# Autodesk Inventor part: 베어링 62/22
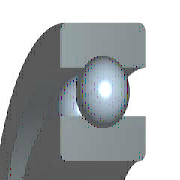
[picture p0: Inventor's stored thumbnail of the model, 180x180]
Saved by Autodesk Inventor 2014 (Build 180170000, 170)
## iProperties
Created: 2009-02
Part Number: 베어링 62/22
Material: 강, 연강
Description: 깊은 그루브 볼 베어링
Document SubType Name: Modeling
Standard: KS B 2023
Designer: KYOUNG IL JANG
Standards Organization: KS
Language: ko-KR
Size Designation: 62/22 - 22 x 50 x 14
Categories: <MemberInstance><Categories><Category DisplayName="샤프트 부품" InternalName="7f7aeb1f-a693-4053-b835-cee3144e0d98" Mnemonic="SHFT"><Category DisplayName="베어링" Inter
Density: 7.86 g/cm^3
Appearance: 강철
Mass: 107.995 g
Surface Area: 96.9171 cm^2
Volume: 13.7399 cm^3
IsCustomPart: 0
Author: KYOUNG IL JANG
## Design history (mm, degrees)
sketch "스케치" dims "d0" = 7.28 (= -0.26 x WD + 0.26 x BD)
  geometry: L1 (3.36, 18)-(10.64, 18); L2 (7, 18)-(7, 14.36); L3 (7, 18)-(7, 21.64); L4 (4.295, 15.564)-(0, 15.564); L5 (0, 11)-(14, 11); L6 (4.295, 20.436)-(0, 20.436); L7 (0, 25)-(14, 25); L8 (14, 11)-(14, 15.564); L9 (9.705, 15.564)-(14, 15.564); L10 (9.705, 20.436)-(14, 20.436); L11 (14, 25)-(14, 20.436); L12 (-1.4, 0)-(8.4, 0) reference; L13 (0, -0.3)-(0, 5.3) reference
  constraints: 22 end point, 4 point on line, 2 collinear, 2 perpendicular, 2 symmetric about line, 1 midpoint, 1 parallel, 14 other
  dimensions: "d9" = 22 diameter of L5 L12 (= WD); "d11" = 50 diameter of L7 L12 (= BD); "d12" = 14 distance between parallel lines of L8 L13 (= KB); "d13" = 31.128 diameter of L9 L12 (= 0.326 x BD + 0.674 x WD)
revolve "본체" stored, may be unused: angle "d6" = 90 deg
revolve "볼" stored, may be unused: angle "d7" = 90 deg
pattern_circular "IDS_ARRAYBALL[SIMPL:T]" dims angle "d3" = 360 deg
body "Solid1"
fillet "모깎기1" dims "d1" = 1 (= KRS)
other parameters: "WD" = 22 [user parameter; used in 5 equation terms], "BD" = 50 [user parameter; used in 5 equation terms], "KB" = 14 [user parameter; used in 1 equation term], "KRS" = 1 [user parameter; used in 1 equation term], "d4" = 0, "d5" = 0, "d8" = 0, "d14" = 0, "d15" = 0, "BBA" = 0 [user parameter], "BC0" = 7154000 [user parameter], "BC" = 1.2233e+07 [user parameter], "BR" = 25 (= 0.5 x BD) [user parameter], "WR" = 11 (= 0.5 x WD) [user parameter]
